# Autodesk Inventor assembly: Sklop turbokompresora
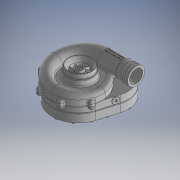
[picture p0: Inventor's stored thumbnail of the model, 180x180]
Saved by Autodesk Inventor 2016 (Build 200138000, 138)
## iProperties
Created: 2015-08
Part Number: Sklop turbokompresora
Document SubType Name: Assembly
Designer: Ugljesa
Author: Ugljesa
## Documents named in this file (19)
- E:\Turbokompr\Sklop turbokompresora.iam
- E:\Turbokompr\rotor turbo kompresosra.ipt
- E:\Turbokompr\Srednji dio kucista.ipt
- E:\Turbokompr\Usini dio kucista.ipt
- E:\Turbokompr\Assembly1\Design Accelerator\Shaft1.iam
- E:\Turbokompr\Assembly1\Design Accelerator\Shaft2.iam
- E:\Turbokompr\Sklop turbokompresora\Design Accelerator\Spur Gears1.iam
- E:\Turbokompr\Sklop turbokompresora\Design Accelerator\Spur Gears3.iam
- E:\Turbokompr\Sklop turbokompresora\Design Accelerator\Key Connection2.iam
- E:\Turbokompr\Sklop turbokompresora\Design Accelerator\Key Connection4.iam
- E:\Turbokompr\Sklop turbokompresora\Design Accelerator\Bearing1.iam
- E:\Turbokompr\Sklop turbokompresora\Design Accelerator\Bearing2.iam
- E:\Turbokompr\Sklop turbokompresora\Design Accelerator\Bearing3.iam
- E:\Turbokompr\Sklop turbokompresora\Design Accelerator\Bearing4.iam
- E:\Turbokompr\Poklopac turbokompresora.ipt
- E:\Turbokompr\Donji dio poklopca.ipt
- E:\Turbokompr\Vijak za ulje.ipt
- E:\Turbokompr\Unbrako - M8 x  60(5).ipt
- E:\Turbokompr\NF E 25-109 - M8 x 16.ipt
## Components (35 placed, 12 different names)
1. rotor turbo kompresosra:1 — Mate:15, Mate:16, Flush:6, Mate:56, Flush:83, Mate:96, Mate:97, Mate:98, Mate:103
2. Srednji dio kucista:1 — Mate:55, Mate:56, Mate:57, Mate:58, Flush:55, Mate:94
3. Usini dio kucista:1 — Mate:20, Mate:57, Mate:58, Mate:103
4. Shaft:1 [sub-assembly] — Mate:31, Flush:7, Mate:44, Flush:9, Mate:160, Mate:161, Flush:84
5. Shaft:2 [sub-assembly] — Mate:15, Mate:16, Mate:20, Mate:30, Flush:6, Flush:8, Mate:44, Mate:55, Mate:91, Flush:80, Mate:92, Flush:81
6. Spur Gears:1 [sub-assembly] — Mate:30, Flush:5, Rotation:1, Flush:8, Angle:1
7. Key Connection:1 [sub-assembly]
8. Spur Gears:2 [sub-assembly] — Mate:31, Mate:32, Mate:33, Flush:5, Rotation:1, Flush:7, Angle:1
9. Key Connection:3 [sub-assembly] — Mate:32, Mate:33
10. Bearing:5 [sub-assembly] — Flush:9, Mate:99, Mate:160
11. Bearing:6 [sub-assembly] — Mate:161, Flush:84
12. Bearing:7 [sub-assembly] — Mate:91, Flush:80, Mate:101
13. Bearing:8 [sub-assembly] — Mate:92, Flush:81
14. Poklopac turbokompresora:1 — Mate:102, Mate:118, Mate:119, Mate:120, Mate:121, Mate:122, Mate:123, Mate:124, Mate:125, Mate:126, Mate:127, Mate:128, Mate:129, Mate:130, Mate:131, Mate:132, Mate:133, Mate:134, Mate:135, Mate:136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
15. Donji dio poklopca:1 — Flush:55, Mate:94, Mate:99, Mate:101, Mate:102, Mate:146, Mate:147, Mate:148, Mate:149, Mate:150, Mate:151, Mate:152, Mate:153, Mate:154, Mate:155, Mate:156, Mate:157, Mate:158, Mate:159, Angle:2
16. Vijak za ulje:1 — Mate:158, Mate:159, Angle:2
17. Unbrako Hex Socket Button Cap - Metric M8 x 60:1 — Mate:126, Mate:137
18. Unbrako Hex Socket Button Cap - Metric M8 x 60:2 — Mate:122, Mate:133
19. Unbrako Hex Socket Button Cap - Metric M8 x 60:3 — Mate:119, Mate:144
20. Unbrako Hex Socket Button Cap - Metric M8 x 60:4 — Mate:118, Mate:143
21. Unbrako Hex Socket Button Cap - Metric M8 x 60:5 — Mate:131, Mate:142
22. Unbrako Hex Socket Button Cap - Metric M8 x 60:6 — Mate:121, Mate:132
23. Unbrako Hex Socket Button Cap - Metric M8 x 60:7 — Mate:130, Mate:141
24. Unbrako Hex Socket Button Cap - Metric M8 x 60:8 — Mate:120, Mate:145
25. Unbrako Hex Socket Button Cap - Metric M8 x 60:9 — Mate:129, Mate:140
26. Unbrako Hex Socket Button Cap - Metric M8 x 60:10 — Mate:128, Mate:139
27. Unbrako Hex Socket Button Cap - Metric M8 x 60:11 — Mate:127, Mate:138
28. Unbrako Hex Socket Button Cap - Metric M8 x 60:12 — Mate:125, Mate:136
29. Unbrako Hex Socket Button Cap - Metric M8 x 60:13 — Mate:123, Mate:134
30. Unbrako Hex Socket Button Cap - Metric M8 x 60:14 — Mate:124, Mate:135
31. NF E 25-109 M8 x 16:1 — Mate:148, Mate:157
32. NF E 25-109 M8 x 16:2 — Mate:149, Mate:156
33. NF E 25-109 M8 x 16:3 — Mate:150, Mate:155
34. NF E 25-109 M8 x 16:4 — Mate:152, Mate:153
35. NF E 25-109 M8 x 16:5 — Mate:151, Mate:154
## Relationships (79: Mate 66, Flush 10, Angle 2, RelateRotation 1)
- Mate:15: rotor turbo kompresosra:1 ↔ Shaft:2
- Mate:16: rotor turbo kompresosra:1 ↔ Shaft:2
- Mate:20: Usini dio kucista:1 ↔ Shaft:2
- Mate:30: Shaft:2 ↔ Spur Gears:1
- Mate:31: Shaft:1 ↔ Spur Gears:2
- Mate:32: Spur Gears:2 ↔ Key Connection:3
- Mate:33: Spur Gears:2 ↔ Key Connection:3
- Flush:5: Spur Gears:1 ↔ Spur Gears:2
- Rotation:1 [RelateRotation]: Spur Gears:1 ↔ Spur Gears:2
- Flush:6: rotor turbo kompresosra:1 ↔ Shaft:2
- Flush:7: Shaft:1 ↔ Spur Gears:2
- Flush:8: Shaft:2 ↔ Spur Gears:1
- Mate:44: Shaft:1 ↔ Shaft:2
- Flush:9: Shaft:1 ↔ Bearing:5
- Mate:55: Srednji dio kucista:1 ↔ Shaft:2
- Mate:56: rotor turbo kompresosra:1 ↔ Srednji dio kucista:1
- Mate:57: Srednji dio kucista:1 ↔ Usini dio kucista:1
- Mate:58: Srednji dio kucista:1 ↔ Usini dio kucista:1
- Flush:55: Srednji dio kucista:1 ↔ Donji dio poklopca:1
- Mate:91: Shaft:2 ↔ Bearing:7
- Flush:80: Shaft:2 ↔ Bearing:7
- Mate:92: Shaft:2 ↔ Bearing:8
- Flush:81: Shaft:2 ↔ Bearing:8
- Mate:94: Srednji dio kucista:1 ↔ Donji dio poklopca:1
- Flush:83: rotor turbo kompresosra:1
- Mate:96: rotor turbo kompresosra:1
- Mate:97: rotor turbo kompresosra:1
- Mate:98: rotor turbo kompresosra:1
- Mate:99: Bearing:5 ↔ Donji dio poklopca:1
- Angle:1: Spur Gears:1 ↔ Spur Gears:2
- Mate:101: Bearing:7 ↔ Donji dio poklopca:1
- Mate:102: Poklopac turbokompresora:1 ↔ Donji dio poklopca:1
- Mate:103: rotor turbo kompresosra:1 ↔ Usini dio kucista:1
- Mate:118: Poklopac turbokompresora:1 ↔ Unbrako Hex Socket Button Cap - Metric M8 x 60:4
- Mate:119: Poklopac turbokompresora:1 ↔ Unbrako Hex Socket Button Cap - Metric M8 x 60:3
- Mate:120: Poklopac turbokompresora:1 ↔ Unbrako Hex Socket Button Cap - Metric M8 x 60:8
- Mate:121: Poklopac turbokompresora:1 ↔ Unbrako Hex Socket Button Cap - Metric M8 x 60:6
- Mate:122: Poklopac turbokompresora:1 ↔ Unbrako Hex Socket Button Cap - Metric M8 x 60:2
- Mate:123: Poklopac turbokompresora:1 ↔ Unbrako Hex Socket Button Cap - Metric M8 x 60:13
- Mate:124: Poklopac turbokompresora:1 ↔ Unbrako Hex Socket Button Cap - Metric M8 x 60:14
- Mate:125: Poklopac turbokompresora:1 ↔ Unbrako Hex Socket Button Cap - Metric M8 x 60:12
- Mate:126: Poklopac turbokompresora:1 ↔ Unbrako Hex Socket Button Cap - Metric M8 x 60:1
- Mate:127: Poklopac turbokompresora:1 ↔ Unbrako Hex Socket Button Cap - Metric M8 x 60:11
- Mate:128: Poklopac turbokompresora:1 ↔ Unbrako Hex Socket Button Cap - Metric M8 x 60:10
- Mate:129: Poklopac turbokompresora:1 ↔ Unbrako Hex Socket Button Cap - Metric M8 x 60:9
- Mate:130: Poklopac turbokompresora:1 ↔ Unbrako Hex Socket Button Cap - Metric M8 x 60:7
- Mate:131: Poklopac turbokompresora:1 ↔ Unbrako Hex Socket Button Cap - Metric M8 x 60:5
- Mate:132: Poklopac turbokompresora:1 ↔ Unbrako Hex Socket Button Cap - Metric M8 x 60:6
- Mate:133: Poklopac turbokompresora:1 ↔ Unbrako Hex Socket Button Cap - Metric M8 x 60:2
- Mate:134: Poklopac turbokompresora:1 ↔ Unbrako Hex Socket Button Cap - Metric M8 x 60:13
- Mate:135: Poklopac turbokompresora:1 ↔ Unbrako Hex Socket Button Cap - Metric M8 x 60:14
- Mate:136: Poklopac turbokompresora:1 ↔ Unbrako Hex Socket Button Cap - Metric M8 x 60:12
- Mate:137: Poklopac turbokompresora:1 ↔ Unbrako Hex Socket Button Cap - Metric M8 x 60:1
- Mate:138: Poklopac turbokompresora:1 ↔ Unbrako Hex Socket Button Cap - Metric M8 x 60:11
- Mate:139: Poklopac turbokompresora:1 ↔ Unbrako Hex Socket Button Cap - Metric M8 x 60:10
- Mate:140: Poklopac turbokompresora:1 ↔ Unbrako Hex Socket Button Cap - Metric M8 x 60:9
- Mate:141: Poklopac turbokompresora:1 ↔ Unbrako Hex Socket Button Cap - Metric M8 x 60:7
- Mate:142: Poklopac turbokompresora:1 ↔ Unbrako Hex Socket Button Cap - Metric M8 x 60:5
- Mate:143: Poklopac turbokompresora:1 ↔ Unbrako Hex Socket Button Cap - Metric M8 x 60:4
- Mate:144: Poklopac turbokompresora:1 ↔ Unbrako Hex Socket Button Cap - Metric M8 x 60:3
- Mate:145: Poklopac turbokompresora:1 ↔ Unbrako Hex Socket Button Cap - Metric M8 x 60:8
- Mate:146: Poklopac turbokompresora:1 ↔ Donji dio poklopca:1
- Mate:147: Poklopac turbokompresora:1 ↔ Donji dio poklopca:1
- Mate:148: Donji dio poklopca:1 ↔ NF E 25-109 M8 x 16:1
- Mate:149: Donji dio poklopca:1 ↔ NF E 25-109 M8 x 16:2
- Mate:150: Donji dio poklopca:1 ↔ NF E 25-109 M8 x 16:3
- Mate:151: Donji dio poklopca:1 ↔ NF E 25-109 M8 x 16:5
- Mate:152: Donji dio poklopca:1 ↔ NF E 25-109 M8 x 16:4
- Mate:153: Donji dio poklopca:1 ↔ NF E 25-109 M8 x 16:4
- Mate:154: Donji dio poklopca:1 ↔ NF E 25-109 M8 x 16:5
- Mate:155: Donji dio poklopca:1 ↔ NF E 25-109 M8 x 16:3
- Mate:156: Donji dio poklopca:1 ↔ NF E 25-109 M8 x 16:2
- Mate:157: Donji dio poklopca:1 ↔ NF E 25-109 M8 x 16:1
- Mate:158: Donji dio poklopca:1 ↔ Vijak za ulje:1
- Mate:159: Donji dio poklopca:1 ↔ Vijak za ulje:1
- Angle:2: Donji dio poklopca:1 ↔ Vijak za ulje:1
- Mate:160: Shaft:1 ↔ Bearing:5
- Mate:161: Shaft:1 ↔ Bearing:6
- Flush:84: Shaft:1 ↔ Bearing:6
